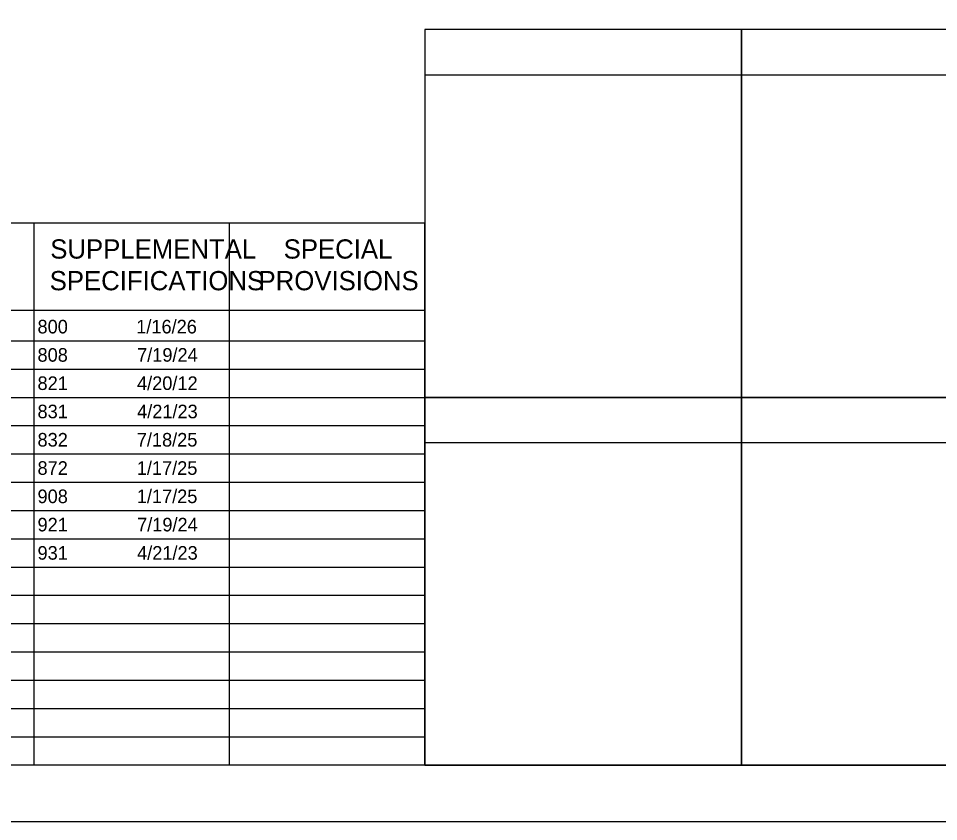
# Model space of a CAD drawing. Extents: x 0 to 34, y 0 to 22.
# Drawn here: x 20.01 to 28.14, y 0 to 7.1 of the extents above; entities that cross this region are included whole.
import ezdxf

# ---------------------------------------------------------------- set-up
doc = ezdxf.new("R2010")
doc.units = 0
for name, color, linetype in [('SH_Border', 7, 'Continuous'), ('SH_Cut_Line', 7, 'Continuous'), ('SH_Data', 7, 'Continuous'), ('SH_Text', 7, 'Continuous')]:
    doc.layers.add(name, color=color, linetype=linetype)

msp = doc.modelspace()

# ---------------------------------------------------------------- linework, layer by layer
at = {"layer": 'SH_Border'}
msp.add_lwpolyline([(1.5, 21.5), (33.5, 21.5), (33.5, 0.5), (1.5, 0.5)], close=True, dxfattribs=at)
at = {"layer": 'SH_Cut_Line'}
msp.add_lwpolyline([(0, 0), (34, 0), (34, 22), (0, 22)], close=True, dxfattribs=at)
at = {"layer": 'SH_Data'}
for p, q in [((23.6, 6.6), (26.4, 6.6)), ((26.4, 6.6), (29.2, 6.6)), ((10.15, 5.2917), (23.6, 5.2917)), ((20.15, 0.5), (20.15, 5.2917)), ((21.875, 0.5), (21.875, 5.2917)), ((23.6, 0.5), (23.6, 5.2917)), ((10.15, 4.5209), (23.6, 4.5209)), ((10.15, 4.25), (23.6, 4.25)), ((10.15, 4), (23.6, 4)), ((10.15, 3.75), (23.6, 3.75)), ((10.15, 3.5), (23.6, 3.5)), ((23.6, 3.35), (26.4, 3.35)), ((26.4, 3.35), (29.2, 3.35)), ((10.15, 3.25), (23.6, 3.25)), ((10.15, 3), (23.6, 3)), ((10.15, 2.75), (23.6, 2.75)), ((10.15, 2.5), (23.6, 2.5)), ((10.15, 2.25), (23.6, 2.25)), ((10.15, 2), (23.6, 2)), ((10.15, 1.75), (23.6, 1.75)), ((10.15, 1.5), (23.6, 1.5)), ((10.15, 1.25), (23.6, 1.25)), ((10.15, 1), (23.6, 1)), ((10.15, 0.75), (23.6, 0.75))]:
    msp.add_line(p, q, dxfattribs=at)
for points in [[(26.4, 7), (23.6, 7), (23.6, 3.75), (26.4, 3.75)], [(29.2, 7), (26.4, 7), (26.4, 3.75), (29.2, 3.75)], [(26.4, 3.75), (23.6, 3.75), (23.6, 0.5), (26.4, 0.5)], [(29.2, 3.75), (26.4, 3.75), (26.4, 0.5), (29.2, 0.5)]]:
    msp.add_lwpolyline(points, close=True, dxfattribs=at)

# ---------------------------------------------------------------- texts
at = {"layer": 'SH_Text'}
for s, height, p in [('SUPPLEMENTAL', 0.17, (20.2925, 4.9763)), ('SPECIAL', 0.17, (22.3542, 4.9763)), ('SPECIFICATIONS', 0.17, (20.2871, 4.6963)), ('PROVISIONS', 0.17, (22.1323, 4.6963)), ('800', 0.12, (20.18, 4.315)), ('1/16/26', 0.12, (21.0522, 4.315)), ('808', 0.12, (20.18, 4.065)), ('7/19/24', 0.12, (21.0597, 4.065)), ('821', 0.12, (20.18, 3.815)), ('4/20/12', 0.12, (21.059, 3.815)), ('831', 0.12, (20.18, 3.565)), ('4/21/23', 0.12, (21.0597, 3.565)), ('832', 0.12, (20.18, 3.315)), ('7/18/25', 0.12, (21.0568, 3.315)), ('872', 0.12, (20.18, 3.065)), ('1/17/25', 0.12, (21.0568, 3.065)), ('908', 0.12, (20.18, 2.815)), ('1/17/25', 0.12, (21.0568, 2.815)), ('921', 0.12, (20.18, 2.565)), ('7/19/24', 0.12, (21.0597, 2.565)), ('4/21/23', 0.12, (21.0597, 2.315)), ('931', 0.12, (20.18, 2.315))]:
    msp.add_text(s, height=height, dxfattribs=at).set_placement(p)

doc.saveas('drawing.dxf')
